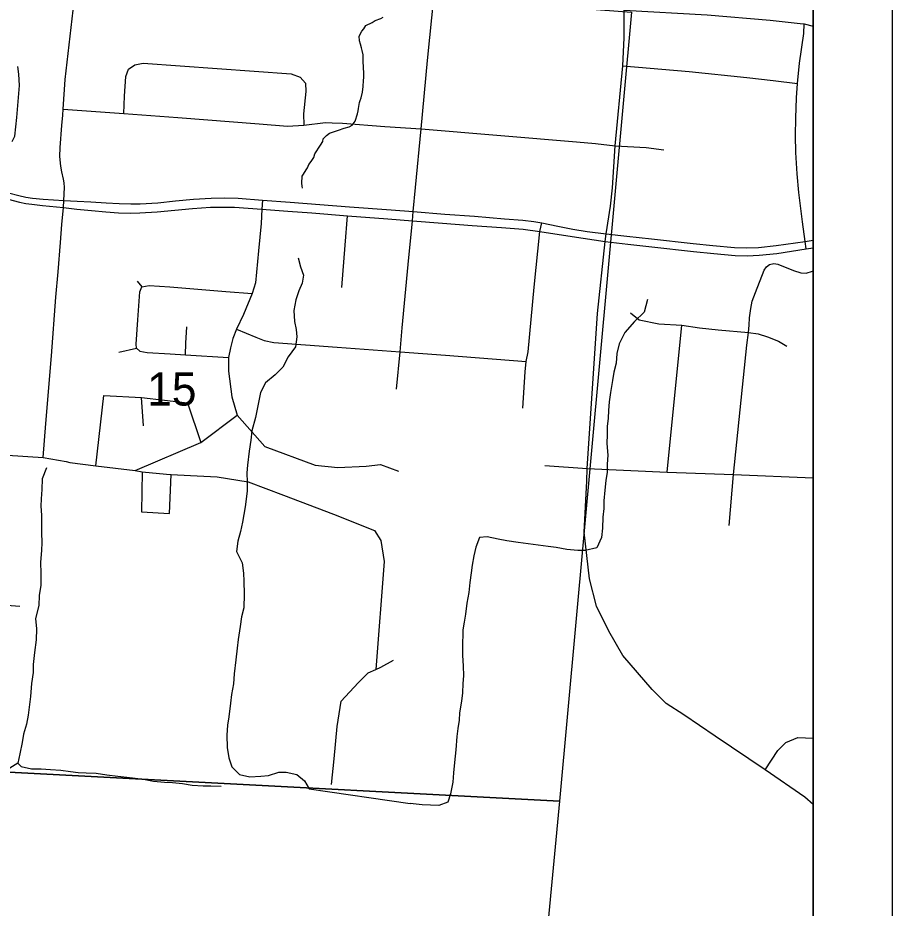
# Model space of a CAD drawing. Extents: x 0 to 34, y 0 to 22.
# Drawn here: x 7.896 to 9, y 15.439 to 16.564 of the extents above; entities that cross this region are included whole.
import ezdxf

# ---------------------------------------------------------------- set-up
doc = ezdxf.new("R2010")
doc.units = 0
for name, color, linetype in [('GM_X_City_Street', 7, 'Continuous'), ('GM_X_Corporation', 7, 'Continuous'), ('GM_X_County_Road', 7, 'Continuous'), ('GM_X_Minor_River', 7, 'Continuous'), ('GM_X_Section_Text', 7, 'Continuous'), ('GM_X_State_Route', 7, 'Continuous'), ('SH_Data', 7, 'Continuous')]:
    doc.layers.add(name, color=color, linetype=linetype)

msp = doc.modelspace()

# ---------------------------------------------------------------- linework, layer by layer
at = {"layer": 'GM_X_City_Street'}
for p, q in [((8.7157, 15.9898), (8.7342, 16.1753)), ((7.9942, 15.9976), (8.0042, 16.0863)), ((8.0544, 16.0481), (8.0517, 16.0839))]:
    msp.add_line(p, q, dxfattribs=at)
for points in [[(8.3741, 16.0947), (8.3786, 16.1417), (8.3812, 16.1722), (8.3887, 16.2521), (8.3939, 16.3074), (8.395, 16.319), (8.3979, 16.3493), (8.4049, 16.4233), (8.413, 16.5096), (8.4215, 16.5931)], [(7.9523, 16.4409), (7.953, 16.4484), (7.9555, 16.4859), (7.9654, 16.5733), (7.9658, 16.5783)], [(8.8913, 16.2716), (8.8901, 16.2812), (8.8869, 16.306), (8.8822, 16.3429), (8.8801, 16.3665), (8.8785, 16.3934), (8.878, 16.4151), (8.8782, 16.4368), (8.8793, 16.4624), (8.8805, 16.4806), (8.8831, 16.5063), (8.8883, 16.5439), (8.8887, 16.5559)], [(8.0297, 16.443), (8.0303, 16.4647), (8.032, 16.4897), (8.0353, 16.4989), (8.0433, 16.5044), (8.0538, 16.5063), (8.2408, 16.493), (8.2524, 16.4889), (8.259, 16.4811), (8.2593, 16.4704), (8.2564, 16.4422), (8.257, 16.428)], [(7.8883, 16.4074), (7.8918, 16.414), (7.8942, 16.4378), (7.8975, 16.4784), (7.8968, 16.4926), (7.8954, 16.502)], [(8.6598, 16.5029), (8.7436, 16.4958), (8.8162, 16.4885), (8.8496, 16.4843), (8.8805, 16.4806)], [(7.953, 16.4484), (8.0297, 16.443), (8.0976, 16.4378), (8.2006, 16.4298), (8.2362, 16.4267), (8.257, 16.428), (8.2843, 16.4314), (8.2925, 16.4311)], [(7.9277, 16.0081), (7.9309, 16.0512), (7.938, 16.1364), (7.9438, 16.2108), (7.9464, 16.2428), (7.9496, 16.2798), (7.9511, 16.3024), (7.9531, 16.3239), (7.9536, 16.333), (7.9544, 16.3492), (7.9541, 16.3551), (7.9533, 16.3599), (7.9512, 16.3691), (7.9499, 16.3764), (7.9488, 16.3885), (7.9491, 16.4), (7.9511, 16.4276), (7.9523, 16.4409)], [(8.2925, 16.4311), (8.3058, 16.4306), (8.3591, 16.4262), (8.4049, 16.4233), (8.6014, 16.4068), (8.6252, 16.4047), (8.6501, 16.4019), (8.6892, 16.3997), (8.7115, 16.3969)], [(8.2045, 16.3335), (8.2039, 16.322), (8.203, 16.3039), (8.1997, 16.2694), (8.1957, 16.2287), (8.1916, 16.2152), (8.1807, 16.1887), (8.1717, 16.1702), (8.167, 16.1586), (8.1641, 16.1468), (8.1617, 16.1346), (8.1616, 16.1174), (8.1659, 16.0847), (8.1728, 16.0618), (8.2076, 16.0221), (8.2712, 15.9984), (8.2996, 15.9955), (8.3357, 15.9974), (8.3537, 15.9993), (8.3765, 15.9908)], [(8.3048, 16.2228), (8.309, 16.2766), (8.3122, 16.3136)], [(8.5336, 16.0706), (8.5365, 16.1166), (8.5378, 16.1294), (8.5404, 16.1417), (8.5478, 16.2235), (8.555, 16.2938), (8.5573, 16.3047)], [(8.794, 15.9222), (8.7996, 15.9867), (8.8163, 16.1501), (8.8185, 16.1661), (8.8194, 16.1752), (8.8199, 16.1846), (8.8213, 16.1964), (8.8231, 16.2055), (8.8275, 16.2167), (8.8383, 16.2447), (8.8413, 16.2491), (8.8451, 16.2521), (8.8504, 16.2533), (8.8555, 16.2523), (8.8752, 16.2444), (8.8846, 16.2413), (8.8915, 16.2409), (8.8992, 16.2434)], [(8.0454, 16.1462), (8.045, 16.1513), (8.0471, 16.182), (8.0498, 16.2173), (8.0524, 16.2237)], [(8.0464, 16.231), (8.0524, 16.2237), (8.0613, 16.2253), (8.0877, 16.2237), (8.1583, 16.2177), (8.1916, 16.2152)], [(8.6695, 16.191), (8.6804, 16.1822), (8.7053, 16.1772), (8.7342, 16.1753), (8.7567, 16.1719), (8.7804, 16.1695), (8.8185, 16.1661), (8.8308, 16.1644), (8.8423, 16.1605), (8.8565, 16.155), (8.867, 16.1488)], [(8.1072, 16.1378), (8.1078, 16.1525), (8.109, 16.1733)], [(8.1717, 16.1702), (8.1962, 16.1602), (8.2068, 16.1559), (8.2191, 16.1535), (8.2989, 16.1475), (8.3786, 16.1417), (8.4358, 16.1374), (8.5378, 16.1294)], [(8.0232, 16.1414), (8.0454, 16.1462), (8.0498, 16.1424), (8.0588, 16.141), (8.0882, 16.139), (8.1072, 16.1378), (8.1617, 16.1346)], [(8.0042, 16.0863), (8.0517, 16.0839), (8.1098, 16.0773), (8.1269, 16.0273)], [(7.9566, 16.0029), (7.9614, 16.002), (7.9942, 15.9976), (8.0436, 15.9919), (8.1269, 16.0273), (8.1728, 16.0618)], [(7.6162, 16.0311), (7.6182, 16.0309), (7.6522, 16.0284), (7.7183, 16.0232), (7.7534, 16.0208), (7.7927, 16.018), (7.8564, 16.0128), (7.9277, 16.0081), (7.9566, 16.0029)], [(8.0436, 15.9919), (8.0525, 15.9902), (8.0833, 15.9872), (8.0892, 15.9867), (8.1137, 15.9854), (8.1473, 15.9837), (8.1864, 15.9775), (8.231, 15.9605), (8.2944, 15.9364), (8.3459, 15.9158), (8.3541, 15.9034), (8.3582, 15.8767), (8.3476, 15.7403)], [(8.0525, 15.9902), (8.0516, 15.9394), (8.0871, 15.9372), (8.0892, 15.9867)], [(8.5611, 15.9981), (8.6149, 15.9944), (8.7157, 15.9898), (8.7996, 15.9867), (8.9, 15.9825)], [(7.2436, 15.8765), (7.3125, 15.87), (7.4395, 15.8634), (7.5713, 15.8528), (7.6394, 15.8403), (7.7046, 15.8353), (7.8316, 15.8254), (7.8435, 15.8245), (7.8982, 15.8203)], [(8.292, 15.5949), (8.2953, 15.6274), (8.2988, 15.6684), (8.3042, 15.7004), (8.3256, 15.7236), (8.338, 15.7361), (8.3476, 15.7403), (8.3541, 15.7432), (8.3701, 15.7521)], [(8.8396, 15.6134), (8.8554, 15.6381), (8.8657, 15.6481), (8.881, 15.6544), (8.9, 15.6537)]]:
    msp.add_lwpolyline(points, dxfattribs=at)
at = {"layer": 'GM_X_Corporation'}
for points in [[(8.9, 14.098), (8.9, 19.3874), (8.8288, 19.3684), (8.73, 19.3298), (8.648, 19.2941), (8.5711, 19.2518), (8.5053, 19.2254), (8.461, 19.2162), (8.3996, 19.2072), (8.3709, 19.2089), (8.3504, 19.2202), (8.3344, 19.2397), (8.3245, 19.2617), (8.3138, 19.2837), (8.3059, 19.2949), (8.2967, 19.3032), (8.274, 19.3267), (8.2293, 19.3521), (8.2346, 19.7113), (8.2412, 20.0451)], [(8.9, 14.098), (8.9, 19.185)]]:
    msp.add_lwpolyline(points, dxfattribs=at)
for points in [[(7.6101, 16.6513), (8.6706, 16.571), (8.5797, 15.5737), (7.5243, 15.6293)], [(7.5243, 15.6293), (8.5797, 15.5737), (8.4854, 14.5806), (8.0353, 14.6105), (7.5723, 14.6206), (7.4312, 14.6313)]]:
    msp.add_lwpolyline(points, close=True, dxfattribs=at)
at = {"layer": 'GM_X_County_Road'}
for points in [[(8.6375, 16.281), (8.6386, 16.2906), (8.6441, 16.3259), (8.6467, 16.3487), (8.6501, 16.4019), (8.6598, 16.5029), (8.6615, 16.5385), (8.6616, 16.5734), (8.6676, 16.6664), (8.6767, 16.7641), (8.7061, 17.0639)], [(8.6616, 16.5734), (8.7664, 16.5673), (8.846, 16.5606), (8.8837, 16.5564)], [(8.8837, 16.5564), (8.8887, 16.5559), (8.9, 16.5533)], [(8.9, 15.5696), (8.8897, 15.579), (8.8396, 15.6134), (8.7765, 15.656), (8.7367, 15.6832), (8.7147, 15.6975), (8.697, 15.7152), (8.6599, 15.7578), (8.6422, 15.7888), (8.6266, 15.8205), (8.6178, 15.855), (8.6109, 15.9137), (8.6141, 15.9781), (8.6149, 15.9944), (8.6277, 16.1899), (8.6375, 16.281)]]:
    msp.add_lwpolyline(points, dxfattribs=at)
at = {"layer": 'GM_X_Minor_River'}
for points in [[(8.2551, 16.3485), (8.2547, 16.3512), (8.2544, 16.3546), (8.2548, 16.3637), (8.2563, 16.3663), (8.2598, 16.3716), (8.2613, 16.3743), (8.2632, 16.3784), (8.2663, 16.3822), (8.2693, 16.3871), (8.2709, 16.392), (8.2781, 16.4026), (8.2808, 16.4075), (8.2812, 16.4109), (8.2854, 16.415), (8.2892, 16.418), (8.3006, 16.4217), (8.3078, 16.4243), (8.3142, 16.4261), (8.3177, 16.428), (8.3215, 16.4333), (8.3246, 16.4423), (8.3254, 16.4461), (8.3258, 16.4491), (8.3273, 16.4567), (8.3281, 16.4594), (8.3293, 16.4628), (8.3308, 16.4699), (8.3316, 16.4768), (8.3321, 16.4843), (8.3325, 16.4881), (8.3325, 16.4942), (8.3322, 16.5007), (8.3319, 16.5094), (8.3319, 16.5128), (8.3316, 16.517), (8.3305, 16.5223), (8.3297, 16.5257), (8.3286, 16.5303), (8.3271, 16.5348), (8.3268, 16.5405), (8.3299, 16.5469), (8.3325, 16.55), (8.3352, 16.5541), (8.3432, 16.5578), (8.347, 16.5604), (8.3542, 16.563), (8.3572, 16.5645)], [(8.2497, 16.2605), (8.2528, 16.249), (8.2563, 16.2386), (8.2548, 16.2284), (8.2504, 16.2186), (8.2466, 16.2073), (8.2443, 16.1937), (8.245, 16.1799), (8.247, 16.17), (8.2479, 16.1605), (8.2464, 16.1479), (8.2369, 16.1353), (8.2305, 16.1225), (8.2207, 16.1125), (8.2086, 16.1026), (8.2021, 16.0902), (8.1986, 16.0736), (8.1959, 16.0588), (8.1912, 16.0418), (8.1898, 16.0301), (8.1878, 16.0161), (8.1858, 15.9986), (8.1848, 15.9888), (8.1852, 15.9769), (8.1852, 15.9659), (8.1842, 15.9553), (8.1828, 15.9458), (8.1792, 15.9265), (8.1769, 15.9148), (8.1735, 15.9023), (8.172, 15.8894), (8.1788, 15.8752), (8.1807, 15.8622), (8.1812, 15.8519), (8.1815, 15.8355), (8.181, 15.818), (8.1783, 15.8067), (8.1765, 15.7946), (8.1737, 15.7783), (8.1726, 15.7673), (8.1711, 15.7525), (8.169, 15.7347), (8.1679, 15.7222), (8.1656, 15.7085), (8.1642, 15.6979), (8.1621, 15.6805), (8.1603, 15.6699), (8.1596, 15.6573), (8.1599, 15.6417), (8.1622, 15.6287), (8.166, 15.6172), (8.1756, 15.6078), (8.1885, 15.6048), (8.2026, 15.6055), (8.2121, 15.6064), (8.2251, 15.6106), (8.2346, 15.6107), (8.2479, 15.6077), (8.2579, 15.5994), (8.2637, 15.5894)], [(8.6911, 16.2077), (8.6869, 16.1919), (8.6747, 16.1801), (8.6622, 16.1663), (8.6553, 16.1517), (8.6523, 16.1396), (8.6512, 16.1275), (8.6485, 16.1161), (8.6467, 16.1055), (8.644, 16.0904), (8.6425, 16.0786), (8.6418, 16.0676), (8.6411, 16.0577), (8.6401, 16.0475), (8.6402, 16.0372), (8.6395, 16.0258), (8.6409, 16.011), (8.6402, 15.9996), (8.6399, 15.9897), (8.6385, 15.9791), (8.637, 15.9669), (8.6359, 15.9536), (8.6356, 15.9438), (8.6345, 15.9328), (8.6341, 15.9187), (8.633, 15.9069), (8.6269, 15.8938), (8.6124, 15.8908), (8.6028, 15.8907), (8.5892, 15.8918), (8.5756, 15.8945), (8.5654, 15.8959), (8.5275, 15.9008), (8.5131, 15.9027), (8.5025, 15.9049), (8.4885, 15.9079), (8.4786, 15.9071), (8.4741, 15.8947), (8.4715, 15.8837), (8.4696, 15.8723), (8.4682, 15.8625), (8.4667, 15.8504), (8.4652, 15.8375), (8.4629, 15.8242), (8.461, 15.8102), (8.4592, 15.8), (8.4577, 15.7905), (8.4571, 15.7677), (8.4572, 15.7578), (8.4583, 15.7448), (8.4587, 15.7323), (8.4577, 15.7224), (8.4573, 15.711), (8.4559, 15.7004), (8.4536, 15.6856), (8.4529, 15.6761), (8.4515, 15.6659), (8.45, 15.6557), (8.4488, 15.6386), (8.4472, 15.6226), (8.446, 15.6097), (8.4449, 15.598), (8.4422, 15.5832), (8.4389, 15.5727), (8.4273, 15.5684), (8.4167, 15.5687), (8.4065, 15.5694), (8.3913, 15.571)], [(7.9317, 15.9951), (7.9264, 15.9812), (7.926, 15.9679), (7.9249, 15.9561), (7.9246, 15.9466), (7.9254, 15.9352), (7.9255, 15.9249), (7.9255, 15.9135), (7.9259, 15.9005), (7.9256, 15.891), (7.9244, 15.8755), (7.9248, 15.8621), (7.9247, 15.8469), (7.9225, 15.8337), (7.9221, 15.8211), (7.9178, 15.8049), (7.9193, 15.7915), (7.9189, 15.7778), (7.9166, 15.7619), (7.915, 15.7468), (7.9151, 15.7365), (7.9128, 15.7225), (7.9115, 15.7062), (7.9105, 15.6959), (7.9086, 15.6827), (7.9067, 15.6713), (7.9029, 15.6585), (7.9011, 15.6482), (7.898, 15.6339), (7.8958, 15.6218), (7.8853, 15.6156)], [(7.8958, 15.6218), (7.8999, 15.6178), (7.9127, 15.6148), (7.9249, 15.6149), (7.937, 15.6141), (7.9499, 15.613), (7.962, 15.6112), (7.9719, 15.6101), (7.9818, 15.6098), (7.9947, 15.6091), (8.0079, 15.6072), (8.0219, 15.6057), (8.0333, 15.6042), (8.0439, 15.6031), (8.0542, 15.6017), (8.067, 15.5991), (8.0807, 15.5979), (8.0909, 15.5976), (8.1034, 15.5962), (8.1159, 15.5943), (8.1296, 15.5931), (8.1395, 15.5932), (8.1524, 15.5929)], [(8.2637, 15.5894), (8.3913, 15.571)]]:
    msp.add_lwpolyline(points, dxfattribs=at)
at = {"layer": 'GM_X_State_Route'}
for points in [[(7.3871, 16.4896), (7.4067, 16.4863), (7.4339, 16.4834), (7.4642, 16.4802), (7.4946, 16.4771), (7.5171, 16.4747), (7.5306, 16.4732), (7.5423, 16.4708), (7.5547, 16.4678), (7.5691, 16.4634), (7.5923, 16.4545), (7.6175, 16.4441), (7.6398, 16.4347), (7.6813, 16.4174), (7.7301, 16.3971), (7.7788, 16.3767), (7.8339, 16.3536), (7.8692, 16.3392), (7.8835, 16.3344), (7.8978, 16.3307), (7.9057, 16.3291), (7.9131, 16.3281), (7.9268, 16.3264), (7.9531, 16.3239)], [(7.8839, 16.3427), (7.8967, 16.3394), (7.9058, 16.3373), (7.9141, 16.336), (7.9274, 16.3346), (7.9536, 16.333), (7.9707, 16.3322), (7.9877, 16.3311), (8.0072, 16.33), (8.0235, 16.3291), (8.0384, 16.3286), (8.0501, 16.3287), (8.0724, 16.33), (8.0949, 16.3324), (8.1174, 16.3344), (8.1397, 16.336), (8.1563, 16.3363), (8.1738, 16.3359), (8.2045, 16.3335), (8.2395, 16.3308), (8.2769, 16.328), (8.3145, 16.325), (8.3673, 16.3211), (8.395, 16.319), (8.435, 16.3158), (8.4726, 16.3129), (8.5105, 16.3099), (8.5333, 16.3079), (8.5475, 16.3064), (8.5573, 16.3047), (8.5776, 16.3005), (8.5968, 16.2967), (8.6146, 16.2938), (8.6386, 16.2906)], [(7.9531, 16.3239), (7.9701, 16.3219), (7.9887, 16.3201), (8.0066, 16.3185), (8.0226, 16.3174), (8.0377, 16.317), (8.0495, 16.3172), (8.0718, 16.3185), (8.0939, 16.3205), (8.1163, 16.3226), (8.1391, 16.3245), (8.1692, 16.3243), (8.2039, 16.322), (8.2366, 16.3195), (8.2668, 16.3172), (8.3122, 16.3136), (8.3631, 16.3099), (8.3939, 16.3074), (8.4319, 16.3042), (8.4694, 16.3014), (8.5066, 16.2986), (8.5337, 16.2966), (8.555, 16.2938), (8.5957, 16.2872), (8.6375, 16.281)], [(8.6375, 16.281), (8.6663, 16.2777), (8.6965, 16.2743), (8.7492, 16.2686), (8.7746, 16.2658), (8.8017, 16.2634), (8.8169, 16.2631), (8.8319, 16.2636), (8.8542, 16.266), (8.8913, 16.2716), (8.9, 16.2729)], [(8.6386, 16.2906), (8.6649, 16.2878), (8.6959, 16.2843), (8.7485, 16.2787), (8.7733, 16.276), (8.8008, 16.2735), (8.8161, 16.2731), (8.8313, 16.2736), (8.8534, 16.276), (8.8901, 16.2812), (8.9, 16.2827)]]:
    msp.add_lwpolyline(points, dxfattribs=at)
at = {"layer": 'SH_Data'}
for p, q in [((9, 20.998), (9, 13.998)), ((8.9, 20.898), (8.9, 14.098))]:
    msp.add_line(p, q, dxfattribs=at)

# ---------------------------------------------------------------- texts
at = {"layer": 'GM_X_Section_Text'}
msp.add_text('15', height=0.04186, rotation=0, dxfattribs=at).set_placement((8.059, 16.0738))

doc.saveas('drawing.dxf')
